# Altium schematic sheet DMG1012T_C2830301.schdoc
size 127 x 101 mm
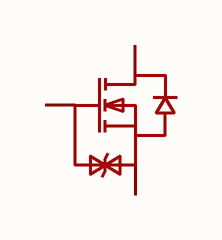
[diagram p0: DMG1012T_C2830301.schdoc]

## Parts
Q?  dmg1012t  [SOT-523-3_L1.6-W0.8-P1.00-LS1.6-BR]  (value not drawn)

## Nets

Not connected (* = marked no-connect by the designer): Q? 1(G) 2(S) 3(D)

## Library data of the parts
Q? = dmg1012t: 数量:1个N沟道;漏源电压(Vdss):20V;连续漏极电流(Id):800mA;导通电阻(RDS(on)):300mΩ@2.5V;耗散功率(Pd):280mW;阈值电压(Vgs(th)):1.1V;; Manufacturer: TECH PUBLIC(台舟); Symbol: DMG1012T_C2830301; AddInBom: yes; ModelId: 3e7fadd59d8d474faa89c2c7e0676879; ModelName: SOT-523-3P_L1.6-W0.8-H0.9-LS1.6-P0.50; ModelTransform: 63.48633,62.992,0,180,0,0,0,0,0; Number: 1个N沟道; Drain to Source Voltage: 20V; Current - Continuous Drain(Id): 800mA; Pd - Power Dissipation: 280mW; Gate Threshold Voltage (Vgs(th)): 1.1V; Input Capacitance(Ciss): 120pF; Reverse Transfer Capacitance (Crss@Vds): 15pF; Type: N沟道; Output Capacitance(Coss): 20pF; Vgs: ±8V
